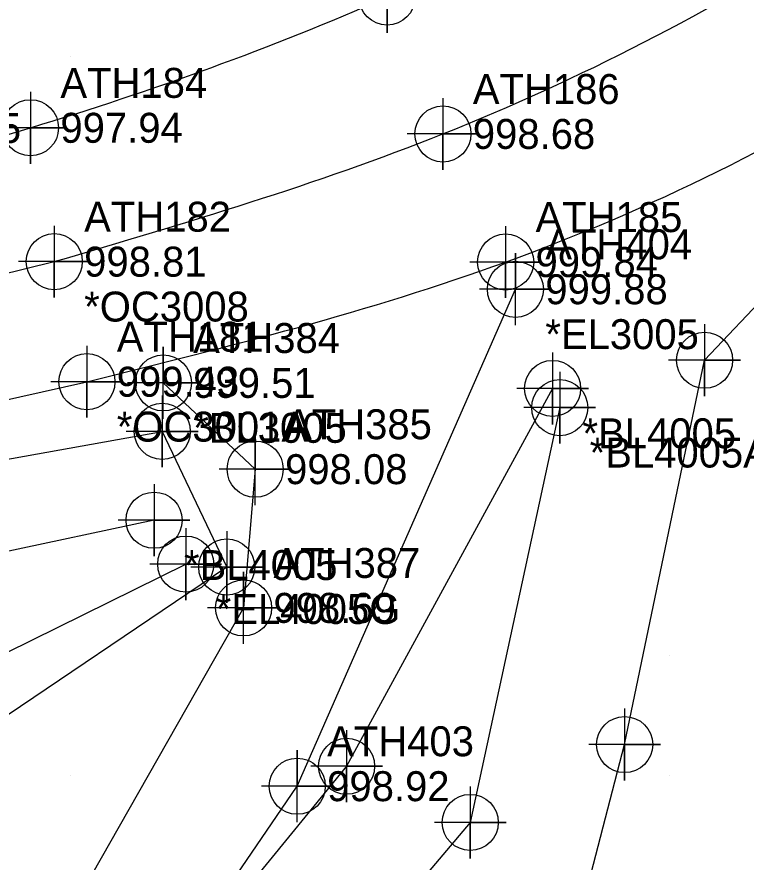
# Model space of a CAD drawing. Extents: x 1116680 to 1117499, y 661040 to 661703.
# Drawn here: x 1117125.5 to 1117186.4, y 661332.7 to 661403.3 of the extents above; entities that cross this region are included whole.
import ezdxf

# ---------------------------------------------------------------- set-up
doc = ezdxf.new("R2010")
doc.units = 0
for name, color, linetype in [('Exist DTM Breakline', 7, 'Continuous'), ('Exist DTM Breakline Cogo Comment', 7, 'Continuous'), ('Exist DTM Breakline Cogo Point CELL', 7, 'Continuous'), ('Exist DTM Crownline', 7, 'Continuous'), ('Exist DTM Crownline Cogo Comment', 7, 'Continuous'), ('Exist DTM Crownline Cogo Elevation', 7, 'Continuous'), ('Exist DTM Crownline Cogo Number', 7, 'Continuous'), ('Exist DTM Crownline Cogo Point CELL', 7, 'Continuous'), ('Exist DTM QL2 LIDAR Elevation Point', 7, 'Continuous'), ('Exist Roads EOP', 7, 'Continuous'), ('Exist Roads EOP Cogo Comment', 7, 'Continuous'), ('Exist Roads EOP Cogo Elevation', 7, 'Continuous'), ('Exist Roads EOP Cogo Number', 7, 'Continuous'), ('Exist Roads EOP Cogo Point CELL', 7, 'Continuous'), ('Exist Roads Soil', 7, 'Continuous'), ('Exist Roads Soil Cogo Comment', 7, 'Continuous'), ('Exist Roads Soil Cogo Elevation', 7, 'Continuous'), ('Exist Roads Soil Cogo Number', 7, 'Continuous'), ('Exist Roads Soil Cogo Point CELL', 7, 'Continuous')]:
    doc.layers.add(name, color=color, linetype=linetype)

msp = doc.modelspace()

# ---------------------------------------------------------------- linework, layer by layer
at = {"layer": 'Exist DTM Breakline'}
msp.add_line((1117136.948, 661361.295), (1117094.014, 661352.219), dxfattribs=at)
for points in [[(1117161.696, 661291.017), (1117168.482, 661312.597), (1117176.266, 661342.559), (1117182.941, 661374.652), (1117194.026, 661386.336), (1117220.943, 661405.14), (1117272.33, 661460.939), (1117291.277, 661496.211), (1117300.472, 661516.498), (1117320.583, 661567.148), (1117342.592, 661626.703), (1117356.346, 661660.105)], [(1117170.247, 661372.296), (1117153.034, 661340.751), (1117143.346, 661328.905), (1117129.964, 661309.196)], [(1117170.843, 661370.689), (1117163.366, 661336.06), (1117151.339, 661321.82), (1117133.997, 661310.363)], [(1117093.445, 661360.799), (1117137.626, 661368.708), (1117143.021, 661357.384), (1117121.473, 661342.844), (1117095.236, 661329.298), (1117090.897, 661311.231), (1117084.978, 661291.24), (1117074.985, 661245.735)], [(1117067.72, 661245.781), (1117079.092, 661299.504), (1117088.264, 661327.406), (1117096.09, 661336.305), (1117116.041, 661346.019), (1117139.594, 661357.628)]]:
    msp.add_lwpolyline(points, dxfattribs=at)
at = {"layer": 'Exist DTM Breakline Cogo Point CELL'}
for points in [[(1117182.941, 661377.652), (1117182.941, 661371.652), (1117182.941, 661374.652), (1117185.941, 661374.652), (1117179.941, 661374.652)], [(1117170.247, 661375.296), (1117170.247, 661369.296), (1117170.247, 661372.296), (1117173.247, 661372.296), (1117167.247, 661372.296)], [(1117170.843, 661373.689), (1117170.843, 661367.689), (1117170.843, 661370.689), (1117173.843, 661370.689), (1117167.843, 661370.689)], [(1117137.626, 661371.708), (1117137.626, 661365.708), (1117137.626, 661368.708), (1117140.626, 661368.708), (1117134.626, 661368.708)], [(1117136.948, 661364.295), (1117136.948, 661358.295), (1117136.948, 661361.295), (1117139.948, 661361.295), (1117133.948, 661361.295)], [(1117139.594, 661360.628), (1117139.594, 661354.628), (1117139.594, 661357.628), (1117142.594, 661357.628), (1117136.594, 661357.628)], [(1117143.021, 661360.384), (1117143.021, 661354.384), (1117143.021, 661357.384), (1117146.021, 661357.384), (1117140.021, 661357.384)], [(1117176.266, 661345.559), (1117176.266, 661339.559), (1117176.266, 661342.559), (1117179.266, 661342.559), (1117173.266, 661342.559)], [(1117153.034, 661343.751), (1117153.034, 661337.751), (1117153.034, 661340.751), (1117156.034, 661340.751), (1117150.034, 661340.751)], [(1117163.366, 661339.06), (1117163.366, 661333.06), (1117163.366, 661336.06), (1117166.366, 661336.06), (1117160.366, 661336.06)]]:
    msp.add_lwpolyline(points, dxfattribs=at)
for centre in [(1117182.941, 661374.652), (1117170.247, 661372.296), (1117170.843, 661370.689), (1117137.626, 661368.708), (1117136.948, 661361.295), (1117139.594, 661357.628), (1117143.021, 661357.384), (1117176.266, 661342.559), (1117153.034, 661340.751), (1117163.366, 661336.06)]:
    msp.add_circle(centre, 2.344, dxfattribs=at)
at = {"layer": 'Exist DTM Crownline'}
msp.add_line((1117090.13, 661373.539), (1117128.608, 661382.881), dxfattribs=at)
msp.add_spline([(1117128.608, 661382.881), (1117161.083, 661393.544), (1117193.928, 661410.345), (1117229.679, 661438.384), (1117257.918, 661472.931), (1117285.234, 661525.056), (1117305.735, 661573.245), (1117329.129, 661633.315)], degree=3, dxfattribs=at)
at = {"layer": 'Exist DTM Crownline Cogo Point CELL'}
for points in [[(1117161.083, 661396.544), (1117161.083, 661390.544), (1117161.083, 661393.544), (1117164.083, 661393.544), (1117158.083, 661393.544)], [(1117128.608, 661385.881), (1117128.608, 661379.881), (1117128.608, 661382.881), (1117131.608, 661382.881), (1117125.608, 661382.881)]]:
    msp.add_lwpolyline(points, dxfattribs=at)
for centre in [(1117161.083, 661393.544), (1117128.608, 661382.881)]:
    msp.add_circle(centre, 2.344, dxfattribs=at)
at = {"layer": 'Exist DTM QL2 LIDAR Elevation Point'}
for p, q in [((1117130, 661400), (1117130, 661400)), ((1117180, 661350), (1117180, 661350)), ((1117130, 661340), (1117130, 661340)), ((1117180, 661340), (1117180, 661340))]:
    msp.add_line(p, q, dxfattribs=at)
at = {"layer": 'Exist Roads EOP'}
msp.add_line((1117084.815, 661362.36), (1117131.334, 661372.856), dxfattribs=at)
for points in [[(1117102.286, 661387.333), (1117126.621, 661394.057), (1117156.418, 661404.979), (1117187.204, 661421.689), (1117219.891, 661448.41), (1117247.012, 661480.823), (1117275.546, 661531.18), (1117296.661, 661577.27), (1117320.803, 661635.676)], [(1117131.334, 661372.856), (1117166.321, 661382.847), (1117200.815, 661399.841), (1117238.067, 661430.322), (1117267.048, 661465.689), (1117295.472, 661519.132), (1117314.821, 661568.418)]]:
    msp.add_spline(points, degree=3, dxfattribs=at)
at = {"layer": 'Exist Roads EOP Cogo Point CELL'}
for points in [[(1117156.418, 661407.979), (1117156.418, 661401.979), (1117156.418, 661404.979), (1117159.418, 661404.979), (1117153.418, 661404.979)], [(1117126.621, 661397.057), (1117126.621, 661391.057), (1117126.621, 661394.057), (1117129.621, 661394.057), (1117123.621, 661394.057)], [(1117166.321, 661385.847), (1117166.321, 661379.847), (1117166.321, 661382.847), (1117169.321, 661382.847), (1117163.321, 661382.847)], [(1117131.334, 661375.856), (1117131.334, 661369.856), (1117131.334, 661372.856), (1117134.334, 661372.856), (1117128.334, 661372.856)]]:
    msp.add_lwpolyline(points, dxfattribs=at)
for centre in [(1117156.418, 661404.979), (1117126.621, 661394.057), (1117166.321, 661382.847), (1117131.334, 661372.856)]:
    msp.add_circle(centre, 2.344, dxfattribs=at)
at = {"layer": 'Exist Roads Soil'}
for points in [[(1117086.62, 661238.672), (1117107.742, 661273.834), (1117132.451, 661314.97), (1117148.912, 661339.084), (1117167.138, 661380.575)], [(1117137.718, 661372.755), (1117145.395, 661365.554), (1117144.424, 661353.972), (1117129.288, 661327.396), (1117114.601, 661300.973), (1117095.553, 661272.762), (1117079.487, 661243.188)]]:
    msp.add_lwpolyline(points, dxfattribs=at)
at = {"layer": 'Exist Roads Soil Cogo Point CELL'}
for points in [[(1117167.138, 661377.575), (1117167.138, 661383.575), (1117167.138, 661380.575), (1117170.138, 661380.575), (1117164.138, 661380.575)], [(1117137.718, 661369.755), (1117137.718, 661375.755), (1117137.718, 661372.755), (1117140.718, 661372.755), (1117134.718, 661372.755)], [(1117145.395, 661362.554), (1117145.395, 661368.554), (1117145.395, 661365.554), (1117148.395, 661365.554), (1117142.395, 661365.554)], [(1117144.424, 661350.972), (1117144.424, 661356.972), (1117144.424, 661353.972), (1117147.424, 661353.972), (1117141.424, 661353.972)], [(1117148.912, 661336.084), (1117148.912, 661342.084), (1117148.912, 661339.084), (1117151.912, 661339.084), (1117145.912, 661339.084)]]:
    msp.add_lwpolyline(points, dxfattribs=at)
for centre in [(1117167.138, 661380.575), (1117137.718, 661372.755), (1117145.395, 661365.554), (1117144.424, 661353.972), (1117148.912, 661339.084)]:
    msp.add_circle(centre, 2.344, dxfattribs=at)

# ---------------------------------------------------------------- texts
at = {"layer": 'Exist DTM Breakline Cogo Comment'}
for s, p in [('*BL4005', (1117113.014, 661392.787)), ('*BL4005', (1117172.747, 661367.296)), ('*BL4005A', (1117173.343, 661365.689)), ('*BL4005', (1117139.448, 661356.295)), ('*EL4005G', (1117142.094, 661352.628))]:
    msp.add_text(s, height=2.5, dxfattribs=at).set_placement(p)
at = {"layer": 'Exist DTM Crownline Cogo Comment'}
msp.add_text('*OC3008', height=2.5, dxfattribs=at).set_placement((1117131.108, 661377.881))
at = {"layer": 'Exist DTM Crownline Cogo Elevation'}
for s, p in [('998.68', (1117163.583, 661392.294)), ('998.81', (1117131.108, 661381.631))]:
    msp.add_text(s, height=2.5, dxfattribs=at).set_placement(p)
at = {"layer": 'Exist DTM Crownline Cogo Number'}
for s, p in [('ATH186', (1117163.583, 661396.044)), ('ATH182', (1117131.108, 661385.381))]:
    msp.add_text(s, height=2.5, dxfattribs=at).set_placement(p)
at = {"layer": 'Exist Roads EOP Cogo Comment'}
msp.add_text('*OC3001A', height=2.5, dxfattribs=at).set_placement((1117133.834, 661367.856))
at = {"layer": 'Exist Roads EOP Cogo Elevation'}
for s, p in [('997.94', (1117129.121, 661392.807)), ('999.84', (1117168.821, 661381.597)), ('999.43', (1117133.834, 661371.606))]:
    msp.add_text(s, height=2.5, dxfattribs=at).set_placement(p)
at = {"layer": 'Exist Roads EOP Cogo Number'}
for s, p in [('ATH184', (1117129.121, 661396.557)), ('ATH185', (1117168.821, 661385.347)), ('ATH181', (1117133.834, 661375.356))]:
    msp.add_text(s, height=2.5, dxfattribs=at).set_placement(p)
at = {"layer": 'Exist Roads Soil Cogo Comment'}
for s, p in [('*EL3005', (1117169.638, 661375.575)), ('*BL3005', (1117140.218, 661367.755))]:
    msp.add_text(s, height=2.5, dxfattribs=at).set_placement(p)
at = {"layer": 'Exist Roads Soil Cogo Elevation'}
for s, p in [('999.88', (1117169.638, 661379.325)), ('999.51', (1117140.218, 661371.505)), ('998.08', (1117147.895, 661364.304)), ('998.69', (1117146.924, 661352.722)), ('998.92', (1117151.412, 661337.834))]:
    msp.add_text(s, height=2.5, dxfattribs=at).set_placement(p)
at = {"layer": 'Exist Roads Soil Cogo Number'}
for s, p in [('ATH404', (1117169.638, 661383.075)), ('ATH384', (1117140.218, 661375.255)), ('ATH385', (1117147.895, 661368.054)), ('ATH387', (1117146.924, 661356.472)), ('ATH403', (1117151.412, 661341.584))]:
    msp.add_text(s, height=2.5, dxfattribs=at).set_placement(p)

doc.saveas('drawing.dxf')
